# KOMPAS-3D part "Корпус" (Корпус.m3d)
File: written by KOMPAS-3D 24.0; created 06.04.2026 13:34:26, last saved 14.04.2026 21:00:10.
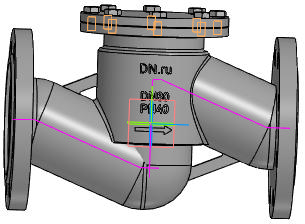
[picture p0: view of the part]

Document properties: Автор: R2D2; Полное имя файла: E:\Работа\Зайцев\VSO3131M-F-S Клапан запорный DN.ru Ду15-100 Ру40\DN80\исходные материалы\Корпус.m3d

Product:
- Body: Труба / Нестандартная труба / L = 159.4 мм  | qty 1
    Материал: Нестандартная труба (density 7856 kg/m3)
    Масса: 32.073646
    Раздел спецификации: Детали
    Примечание: 7,96 кг
    additional columns: Pipeline; 0.09; 0; 0; 0.002; 0.1594; true; 0.04
- Body: Труба / Нестандартная труба / L = 204.9 мм  | qty 1
    Материал: Нестандартная труба (density 7856 kg/m3)
    Масса: 32.073646
    Раздел спецификации: Детали
    Примечание: 10,24 кг
    additional columns: Pipeline; 0.09; 0; 0; 0.002; 0.20491; true; 0.04
- Body: Тело 4  | qty 1
    Материал: Нестандартная труба (density 7856 kg/m3)
    Масса: 32.073646
- Body: Тело 5  | qty 1
    Материал: Нестандартная труба (density 7856 kg/m3)
    Масса: 32.073646
- Body: Тело 8  | qty 1
    Материал: Нестандартная труба (density 7856 kg/m3)
    Масса: 32.073646
- Body: Тело 9  | qty 1
    Материал: Нестандартная труба (density 7856 kg/m3)
    Масса: 32.073646
- Component [standard]: Hexagon head screw ISO 4017 - М10 x 20  | qty 8  | Масса: 0.023019; Рассекать на разрезах: no; source file: C:\Program Files\ASCON\KOMPAS-3D v24\Libs\PolynomLib\DATA\vault\Methods\Kompas\3D\PLib_Bolt_1_ISO_1100.m3d
- Part/product: Корпус
    Масса: 6.9

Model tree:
1. Труба
2. Труба:1  (labels: {F703FF30-5BE6-4673-A7F1-8EDA1BE1E2D1}; SHAPEOBJECT3D_ATTR_BUTT; SHAPEOBJECT3D_ATTR_VALID; SHAPEOBJECT3D_ATTR_BUTT_AREA)
     PIPE_R = 7
3. Труба:2  (labels: {F703FF30-5BE6-4673-A7F1-8EDA1BE1E2D1}; SHAPEOBJECT3D_ATTR_BUTT; SHAPEOBJECT3D_ATTR_VALID; SHAPEOBJECT3D_ATTR_BUTT_AREA)
     PIPE_R = 5
4. Колонна
5. Элемент выдавливания:1
     Смещение 1 = -1; Смещение 2 = -5
6. Скругление:17  (with: Ребро.Элемент выдавливания:1)
     Радиус = 1
7. Скругление:18  (with: Ребро.Элемент выдавливания:1)
8. Скругление:24  (with: Ребро.Скругление:18, Ребро.Элемент выдавливания:1)
     Радиус = 1
9. Элемент выдавливания:2
     Расстояние 1 = 6
10. Скругление:19  (with: Ребро.Элемент выдавливания:2)
     Радиус = 2
11. Эскиз:4  (with: Грань.Элемент выдавливания:1)
12. Элемент выдавливания:3
     Расстояние 1 = 17.5
13. Скругление:21  (with: Ребро.Элемент выдавливания:3)
14. ОТЛИВКА
15. Скругление:6  (with: Грань.Элемент выдавливания:1)
     Радиус = 2
16. Элемент выдавливания:6  (with: Грань.Элемент выдавливания:1)
     Смещение 1 = 4
17. ЛЕЙБЛ
18. Элемент выдавливания:7  (with: Грань.Элемент выдавливания:1)
     Расстояние 1 = 60.9817; Смещение 1 = 1
19. Фланец верх  (with: Ребро.Элемент выдавливания:3)
20. Элемент вращения:2
     Угол 1 = 360
21. Эскиз:12  (with: Грань.Элемент вращения:2)
22. Элемент выдавливания:9  (with: Грань.Элемент вращения:2)
     Расстояние 2 = 20
23. Массив по концентрической сетке:1  (with: Элемент выдавливания:9, Эскиз:12, Грань.Элемент вращения:2)  (8 pattern instances)
     Шаг 2 = 360
24. Фланец
25. Элемент вращения:1
     Угол 1 = 360
26. отвертие во фланце  (with: Грань.Элемент вращения:1)
27. Элемент выдавливания:8
28. Массив по концентрической сетке:2  (with: Элемент выдавливания:8, Эскиз:10, Грань.Элемент вращения:1)  (8 pattern instances)
     Шаг 2 = 360
29. Зеркальный массив:1
30. Экземпляр ( 1 )
31. Экземпляр ( 2 )  (with: Элемент вращения:1, Массив по концентрической сетке:2, Экземпляр ( 1 ), Элемент выдавливания:8)
32. Экземпляр ( 3 )  (with: Элемент выдавливания:8)
33. Экземпляр ( 4 )  (with: Элемент выдавливания:8)
34. Экземпляр ( 5 )  (with: Элемент выдавливания:8)
35. Экземпляр ( 6 )  (with: Элемент выдавливания:8)
36. Экземпляр ( 7 )  (with: Элемент выдавливания:8)
37. Экземпляр ( 8 )  (with: Элемент выдавливания:8)
38. Скругление:25  (with: Ребро.Элемент вращения:2)
     Радиус = 2
39. Скругление:26  (with: Массив по концентрической сетке:1, Грань.Элемент вращения:2)  (labels: Грань.Элемент выдавливания:9.Экземпляр ( 1, 3 ))  (8 pattern instances)
     Радиус = 2; N 1 = 1; Шаг 1 = 10; Шаг 2 = 360; Номер 1 = 1

Expressions: DS/2+3; D1/2; DN/2; D/2; DS-v977*4; LL/2; D1-v1234*2
Referenced files in C:\Program Files\ASCON\KOMPAS-3D v24\Libs\Pipeline\: StylesTemplate.a3d, TemplateHPH, InsulationStylesTemplate.a3d, Insulation
Referenced files in C:\Program Files\ASCON\KOMPAS-3D v24\Templates\: Констр. чертеж А3 гориз. перв. лист.cdt
Referenced files in E:\Работа\Зайцев\VSO3131M-F-S Клапан запорный DN.ru Ду15-100 Ру40\DN20\исходные материалы\: 
Referenced files in C:\Program Files\ASCON\KOMPAS-3D v24\Libs\PolynomLib\DATA\vault\Methods\Kompas\3D\: PLib_Bolt_1_ISO_1100.m3d
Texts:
  Отводы ГОСТ 17375-2001
  Констр. чертеж А3 гориз. перв. лист.cdt
  BOSimple***PART:c031cb5e-65ec-2f83-1ced-75228c8ad34f***PART:A259_7B16EF33AB1642D2[16;1,5;20;10;-;Undefined]
  GOST 26.020 Pr3
  var3D
  смещение колонны вниз
  LL-10
  DN+10
  Hexagon head screw ISO 4017 - М10 x 20 (1)
  hole1
  hole2
  Труба / Нестандартная труба / L = %s мм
